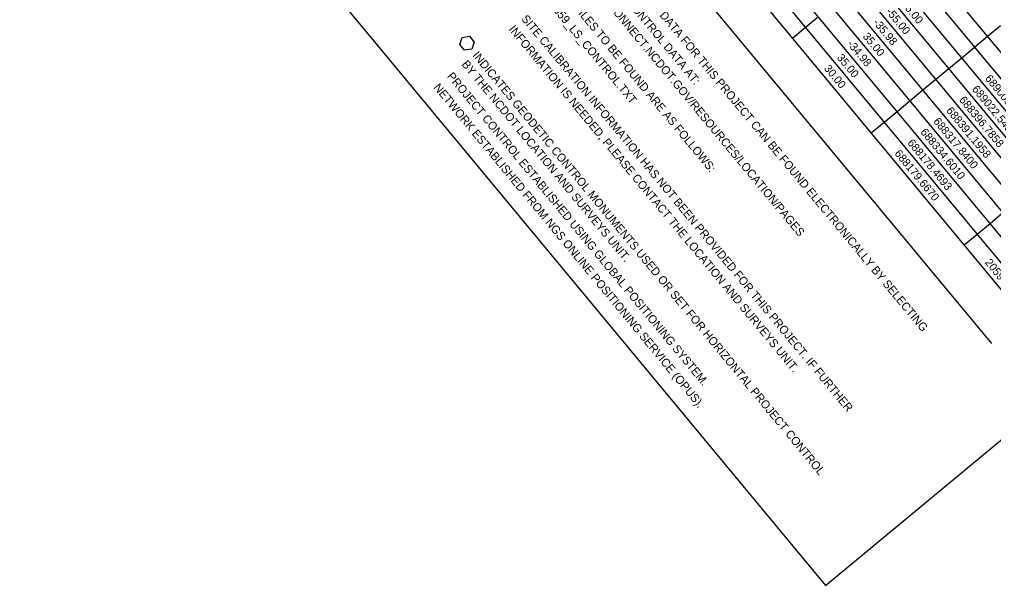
# Model space of a CAD drawing. Extents: x 2057130 to 2060012, y 687175 to 689912.
# Drawn here: x 2057863 to 2058941, y 687175 to 687802 of the extents above; entities that cross this region are included whole.
import ezdxf

# ---------------------------------------------------------------- set-up
doc = ezdxf.new("R2010")
doc.units = 0
for name, color, linetype in [('CTL GPS Horizontal CELL', 7, 'Continuous'), ('CTL Sheet Border CELL', 7, 'Continuous'), ('CTL Sheet Notes CELL', 7, 'Continuous'), ('CTL Sheet Table Cell', 7, 'Continuous'), ('CTL Sheet Text', 7, 'Continuous')]:
    doc.layers.add(name, color=color, linetype=linetype)

msp = doc.modelspace()

# ---------------------------------------------------------------- linework, layer by layer
at = {"layer": 'CTL GPS Horizontal CELL'}
msp.add_line((2058358.1, 687775.1), (2058358.1, 687775.1), dxfattribs=at)
msp.add_lwpolyline([(2058350, 687773.8), (2058352.9, 687781.5), (2058361, 687782.9), (2058366.2, 687776.5), (2058363.4, 687768.7), (2058355.2, 687767.4), (2058350, 687773.8)], dxfattribs=at)
at = {"layer": 'CTL Sheet Border CELL'}
msp.add_lwpolyline([(2059967.3, 688179.9), (2058531.1, 689911.9), (2057318.7, 688906.6), (2058754.9, 687174.6)], close=True, dxfattribs=at)
at = {"layer": 'CTL Sheet Notes CELL'}
msp.add_line((2058526.1, 687940.2), (2058938.9, 687442.5), dxfattribs=at)
at = {"layer": 'CTL Sheet Table Cell'}
for p, q in [((2058696.9, 688068.9), (2059140.2, 687534.3)), ((2058682.6, 688057), (2059125.9, 687522.4)), ((2058668.3, 688045.1), (2059111.6, 687510.6)), ((2058654, 688033.2), (2059097.3, 687498.7)), ((2058639.6, 688021.4), (2059082.9, 687486.8)), ((2058625.3, 688009.5), (2059068.6, 687474.9)), ((2058611, 687997.6), (2059054.3, 687463.1)), ((2058596.7, 687985.7), (2059040, 687451.2)), ((2058582.4, 687973.9), (2059025.7, 687439.3)), ((2058568.1, 687962), (2059011.3, 687427.4)), ((2058747.1, 687804.4), (2058732.8, 687792.5)), ((2058732.8, 687792.5), (2058718.5, 687780.6)), ((2058948.7, 687794.4), (2058934.4, 687782.5)), ((2058934.4, 687782.5), (2058920.1, 687770.6)), ((2058920.1, 687770.6), (2058905.8, 687758.7)), ((2058905.8, 687758.7), (2058891.4, 687746.9)), ((2058891.4, 687746.9), (2058877.1, 687735)), ((2058877.1, 687735), (2058862.8, 687723.1)), ((2058862.8, 687723.1), (2058848.5, 687711.2)), ((2058848.5, 687711.2), (2058834.2, 687699.4)), ((2058834.2, 687699.4), (2058819.9, 687687.5)), ((2058819.9, 687687.5), (2058805.5, 687675.6)), ((2058951.4, 687587.2), (2058937.1, 687575.3)), ((2058937.1, 687575.3), (2058922.8, 687563.4)), ((2058922.8, 687563.4), (2058908.4, 687551.5))]:
    msp.add_line(p, q, dxfattribs=at)

# ---------------------------------------------------------------- texts
at = {"layer": 'CTL Sheet Notes CELL'}
for s, rotation, p in [('1.    THE CONTROL DATA FOR THIS PROJECT CAN BE FOUND ELECTRONICALLY BY SELECTING', 309.6672, (2058497.1, 687895)), ('PROJECT CONTROL DATA AT:', 309.6672, (2058495.5, 687866.5)), ('HTTPS://CONNECT.NCDOT.GOV/RESOURCES/LOCATION/PAGES', 309.6672, (2058481.4, 687854.9)), ('THE FILES TO BE FOUND ARE AS FOLLOWS:', 309.6672, (2058458.1, 687835.5)), ('B4659_LS_CONTROL.TXT', 309.6672, (2058443.4, 687823.3)), ('SITE CALIBRATION INFORMATION HAS NOT BEEN PROVIDED FOR THIS PROJECT. IF FURTHER', 309.6672, (2058417.7, 687802)), ('INFORMATION IS NEEDED, PLEASE CONTACT THE LOCATION AND SURVEYS UNIT.', 309.6672, (2058403.7, 687790.4)), ('INDICATES GEODETIC CONTROL MONUMENTS USED OR SET FOR HORIZONTAL PROJECT CONTROL', 309.562, (2058363.5, 687761.5)), ('BY THE NCDOT LOCATION AND SURVEYS UNIT.', 309.562, (2058351.6, 687751.7)), ('PROJECT CONTROL ESTABLISHED USING GLOBAL POSITIONING SYSTEM.', 309.562, (2058335.5, 687738.4)), ('NETWORK ESTABLISHED FROM NGS ONLINE POSITIONING SERVICE (OPUS).', 309.562, (2058320.6, 687726))]:
    msp.add_text(s, height=9.195, rotation=rotation, dxfattribs=at).set_placement(p)
at = {"layer": 'CTL Sheet Text'}
for s, height, p in [('-55.00', 8.86, (2058835.8, 687821.6)), ('-55.00', 8.86, (2058821.4, 687809.8)), ('-35.98', 8.86, (2058807.1, 687797.9)), ('35.00', 8.86, (2058795.6, 687782.6)), ('-34.98', 8.86, (2058778.5, 687774.2)), ('35.00', 8.86, (2058767, 687758.9)), ('30.00', 8.86, (2058752.7, 687747)), ('689009.2378', 8.858, (2058931, 687735.9)), ('689022.5437', 8.858, (2058916.7, 687724)), ('688396.7858', 8.858, (2058902.4, 687712.1)), ('688391.1958', 8.858, (2058888.1, 687700.3)), ('688317.8400', 8.858, (2058873.8, 687688.4)), ('688334.6010', 8.858, (2058859.5, 687676.5)), ('688178.4693', 8.858, (2058845.1, 687664.6)), ('688179.6670', 8.858, (2058830.8, 687652.8)), ('2059067.7139', 8.858, (2058930.9, 687532.1))]:
    msp.add_text(s, height=height, rotation=309.6672, dxfattribs=at).set_placement(p)

doc.saveas('drawing.dxf')
